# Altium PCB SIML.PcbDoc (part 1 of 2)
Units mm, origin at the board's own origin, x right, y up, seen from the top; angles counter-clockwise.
Board outline 80.5 x 51.25 mm, 2 copper layers (Top Layer, Top, Bottom Layer, Bottom), stack 1.571 mm thick; 94 components, 58 nets, 279 pads, 160 vias.
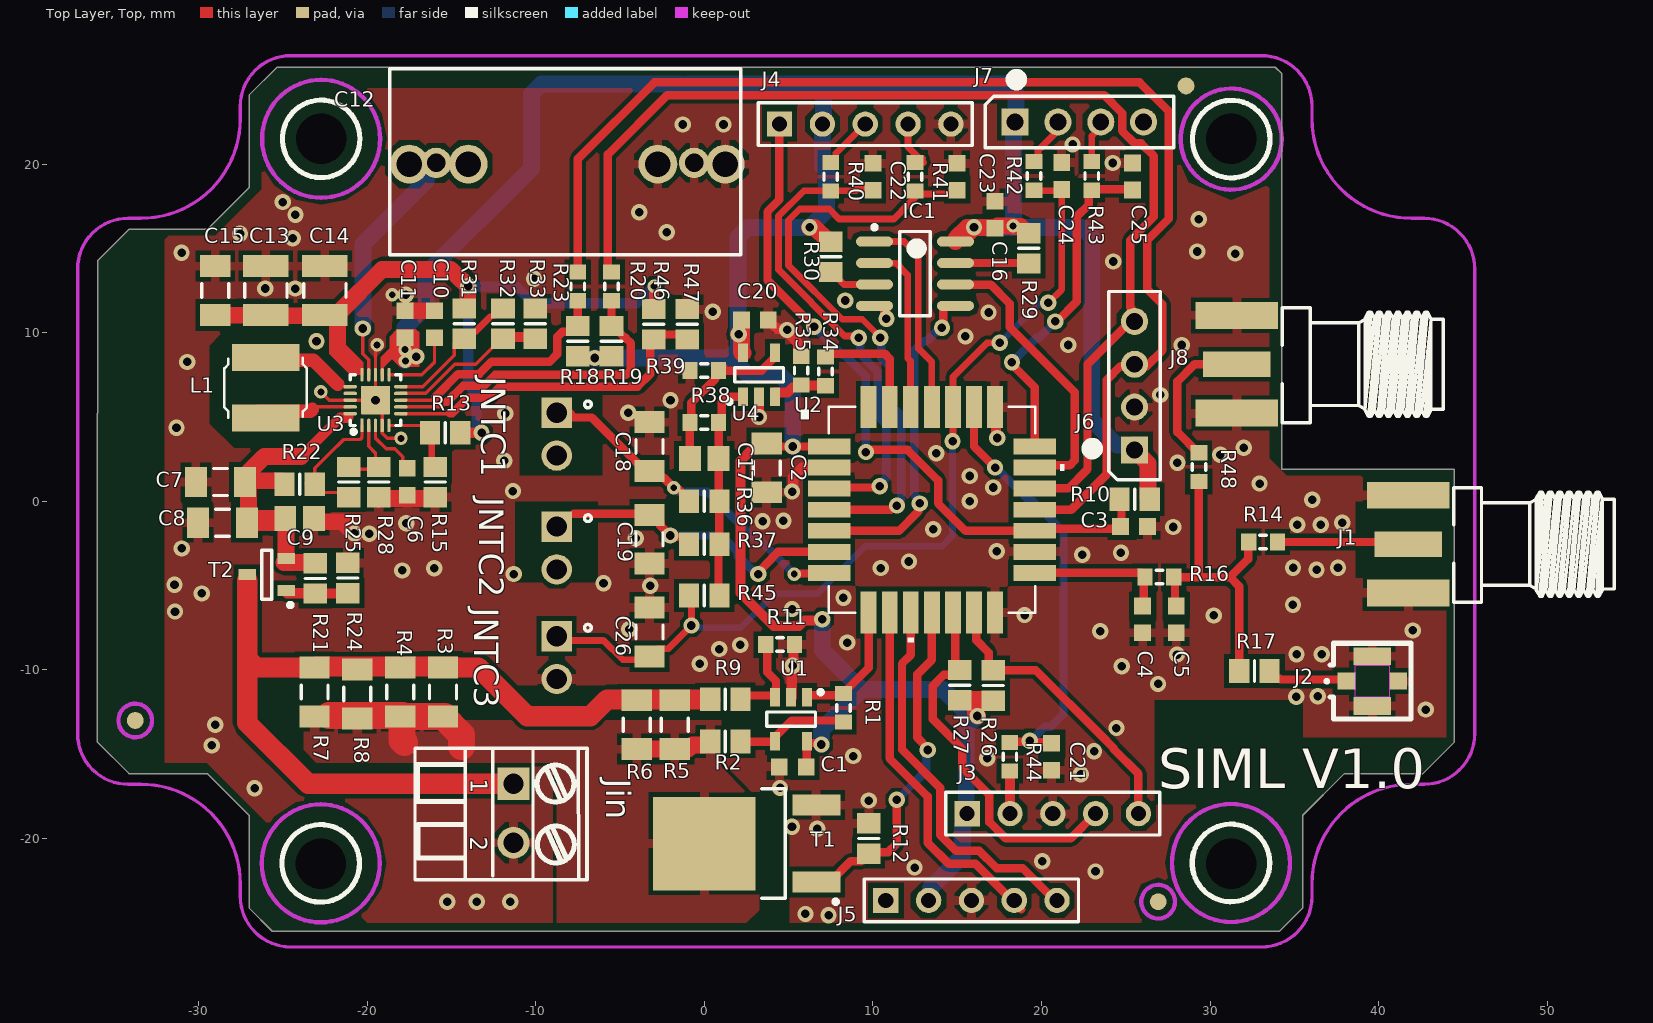
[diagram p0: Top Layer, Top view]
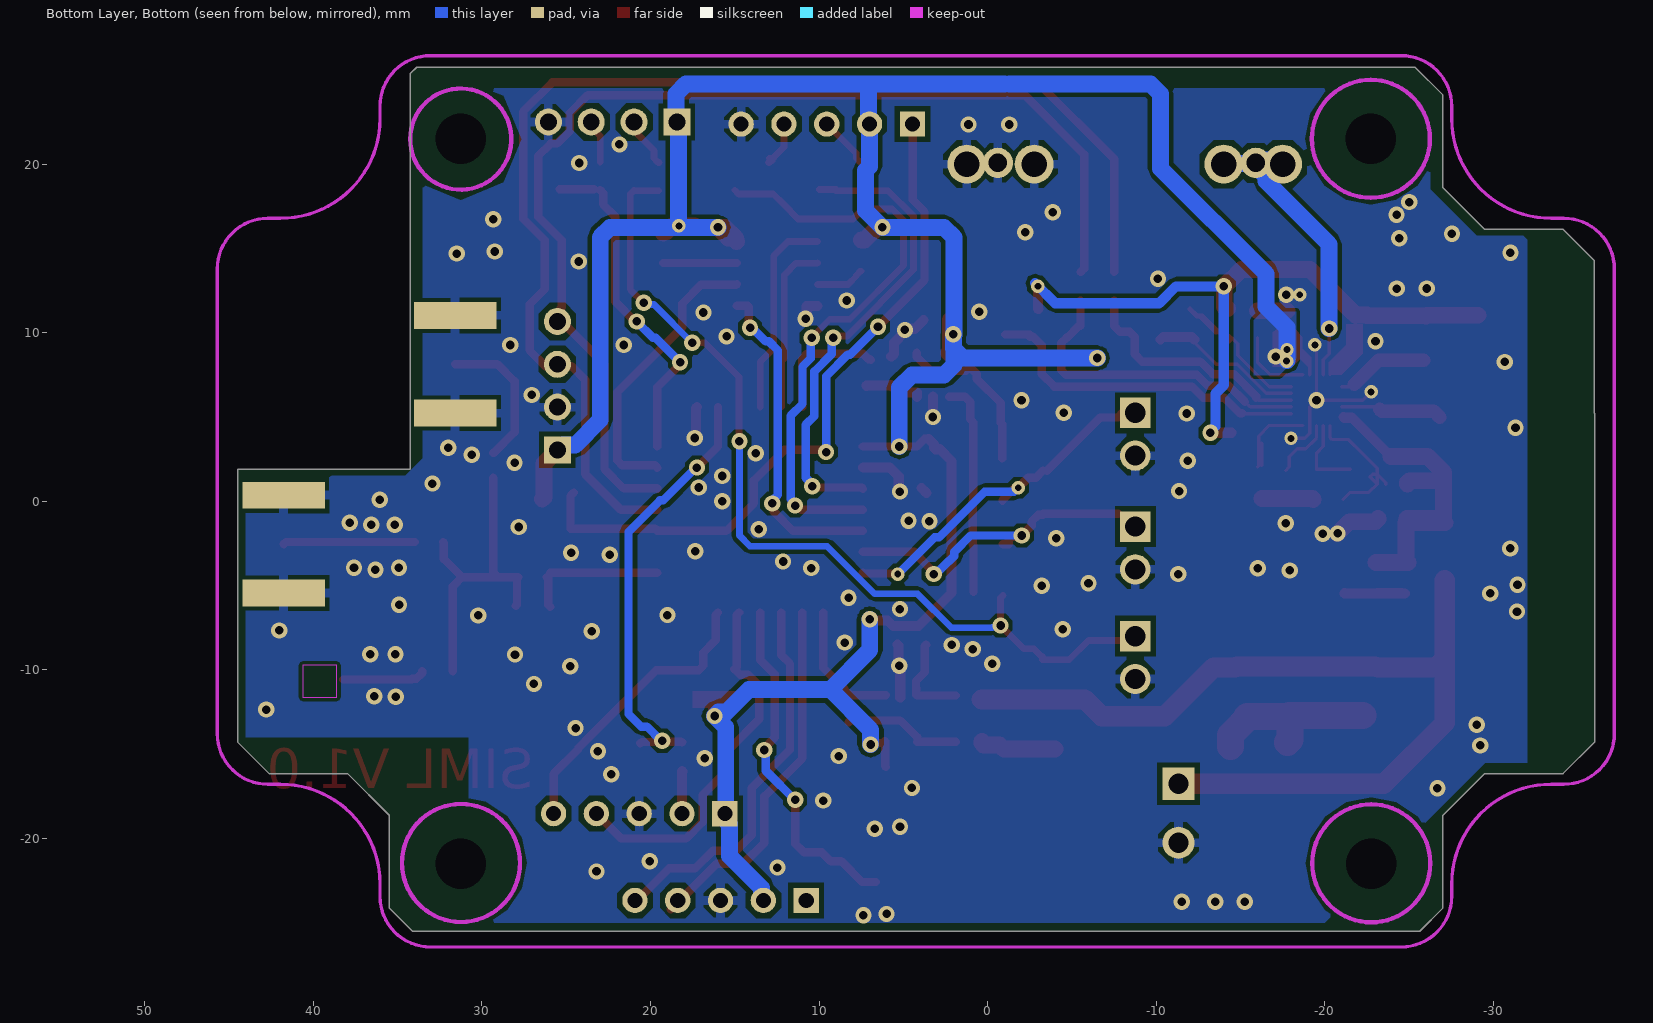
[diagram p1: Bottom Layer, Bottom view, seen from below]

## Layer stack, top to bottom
Top Solder, Top Mask: solder mask 0.0102, Solder Resist, Dk 3.5
Top Layer, Top: signal copper 0.0356
Dielectric 1: dielectric 1.5, FR-4, Dk 4.8
Bottom Layer, Bottom: signal copper 0.0356
Bottom Solder, Bot Mask: solder mask 0.0102, Solder Resist, Dk 3.5

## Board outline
-34.125,-16.15 -29.475,-16.15 -27,-18.625 -27,-24.125 -25.625,-25.5 34.125,-25.5 35.5,-24.125 35.5,-18.625 37.975,-16.15 42.625,-16.15 44.5,-14.275 44.5,1.905 34.25,1.905 34.25,25.375 33.875,25.75 -25.35,25.75 -26.975,24.125 -26.975,18.625 -29.45,16.15 -34.1,16.15 -35.975,14.275 -35.975,5.225 -36,5.225 -36,-14.275

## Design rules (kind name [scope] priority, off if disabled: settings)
Clearance Clearance_1 [All] p1: gap=0.22 ignorepadtopadclearanceinfootprint=FALSE except(0.2: Arc-SMDPad Track-Track Track-SMDPad SMDPad-SMDPad; 0.3: SMDPad-Poly THPad-Poly THPad-Region)
PlaneClearance [All] p1: clearance=0.254
PolygonConnect [All] p1: thpad.connectstyle=Relief thpad.reliefconductorwidth=0.54 thpad.reliefentries=4 thpad.polygonreliefangle="90 Angle" thpad.airgapwidth=0.254 smdpad.connectstyle=Relief smdpad.reliefconductorwidth=0.54 smdpad.reliefentries=4 smdpad.polygonreliefangle="90 Angle" smdpad.airgapwidth=0.254 via.connectstyle=Direct via.reliefconductorwidth=0.254 via.reliefentries=4 via.polygonreliefangle="90 Angle" via.airgapwidth=0.254
RoutingVias [All] p1: holewidth=1 width=1 viastyle="Through Hole" minholewidth=0.35 minwidth=0.8 maxholewidth=0.711 maxwidth=1.27
SilkToSilkClearance [All] p1: silktosilkclearance=0.1
SilkToSolderMaskClearance [IsPad] p1: minsilkscreentomaskgap=0.08 clearancetoexposedcopper=TRUE
SolderMaskExpansion [All] p1: expansion=0.102 istentingtop=FALSE
SupplyNets "Schematic Supply Nets_1" [InNet('3.3V')] p1: voltage=0.000
SupplyNets "Schematic Supply Nets" [InNet('GND')] p2: voltage=0.000
Width [All] p1: maxlimit=7.62 minlimit=0.2 preferedwidth=0.381
27 further rules are at their usual default settings.

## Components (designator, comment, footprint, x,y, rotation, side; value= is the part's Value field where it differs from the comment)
C1 "100nF" CAPC1608N 5.25,-15.75 r0 top
C2 "4.7uF" CAPC3216N 3.7,1.986 r90 top
C3 "100nF" CAPC1608N 25.5,-1.5 r180 top
C4 "N.M" CAPC1608N 26,-7 r90 top
C5 "N.M" CAPC1608N 28,-7 r90 top
C6 "10nF" CAPC1608N -17.613,1.163 r270 top
C7 "4.7uF" CAPC3216N -28.702,1.143 r0 top
C8 "4.7uF" CAPC3216N -28.575,-1.27 r0 top
C9 "N.M." CAPC2012N -24.003,-1.016 r180 top
C10 "100nF" CAPC1608N -16,10.5 r270 top
C11 "100nF" CAPC1608N -17.75,10.5 r270 top
C12 "5F" CAPR1530x1050X2050X2800 -8.25,20.075 r0 top locked
C13 "22uF" CAPC3225N -26,12.5 r270 top
C14 "22uF" CAPC3225N -22.5,12.5 r270 top
C15 "4.7uF" CAPC3216N -29,12.5 r270 top
C16 "100nF" CAPC1608N 17.25,17 r270 top
C17 "N.M." CAPC2012N 0,2.54 r0 top
C18 "4.7uF" CAPC3216N -3.25,3.25 r270 top
C19 "4.7uF" CAPC3216N -3.25,-2.25 r90 top
C20 "100nF" CAPC1608N 3,10.75 r180 top
C21 "N.M" CAPC1608N 20.6,-15.15 r270 top
C22 "N.M" CAPC1608N 10,19.25 r90 top
C23 "N.M" CAPC1608N 15,19.25 r90 top
C24 "N.M" CAPC1608N 21.209,19.304 r90 top
C25 "N.M" CAPC1608N 25.398,19.27 r90 top
C26 "4.7uF" CAPC3216N -3.25,-7.75 r270 top
IC1 "W25Q64JVSSIQ" SOIC127P600-8N 12.5,13.5 r0 top
J1 "SMA JACJK_EDGE_female" "Adam Tech_RF2-143-T-17-50-G" 43.18,-2.54 r180 top
J2 "U.FL-JACK_male" LINX_CONMHF1-SMD-T 39.624,-10.668 r90 top
J3 "HEADER 1X5" HDR1X5 20.675,-18.525 r0 top
J4 "HEADER 1X5" HDR1X5 9.55,22.375 r0 top
J5 "HEADER 1X5" HDR1X5 15.85,-23.675 r0 top
J6 "Header Female" HARWIN_M20-7820442 25.527,6.858 r90 top locked
J7 "Header Female" HARWIN_M20-7820442 22.25,22.5 r0 top
J8 "SMA JACJK_EDGE_female" "Adam Tech_RF2-143-T-17-50-G" 33.02,8.128 r180 top
Jin "DG381S" DEGSON_DG381S-3.5-02P-14-00AH -9,-18.5 r270 top
JNTC1 "CI31 Series 2.54mm(.100\")" CVILUX_CI3102P1V00 -8.75,5.25 r270 top
JNTC2 "CI31 Series 2.54mm(.100\")" CVILUX_CI3102P1V00 -8.75,-1.5 r270 top
JNTC3 "CI31 Series 2.54mm(.100\")" CVILUX_CI3102P1V00 -8.75,-8 r270 top
L1 "22uH" IND_Taiyo_NRS5024 -26.018,6.733 r90 top
R1 "49K9" RESC1608N(0603) 8.25,-12.25 r90 top
R2 "4K99" RESC2012N(0805) 1.25,-14.25 r0 top
R3 "1R" RESC3216N(1206) -15.494,-11.303 r270 top
R4 "1R" RESC3216N(1206) -18.034,-11.303 r270 top
R5 "1R" RESC3216N(1206) -1.75,-13.25 r270 top
R6 "1R" RESC3216N(1206) -4,-13.25 r270 top
R7 "1R" RESC3216N(1206) -23.114,-11.303 r270 top
R8 "1R" RESC3216N(1206) -20.574,-11.43 r270 top
R9 "4K99" RESC2012N(0805) 1.25,-11.75 r0 top
R10 "4K99" RESC2012N(0805) 25.527,0.127 r0 top
R11 "49K9" RESC1608N(0603) 4.5,-8.5 r180 top
R12 "4K99" RESC2012N(0805) 9.75,-20 r270 top
R13 "N.M." RESC2012N(0805) -15.367,4.064 r0 top
R14 "0R" RESC1608N(0603) 33.147,-2.413 r0 top
R15 "4K99" RESC2012N(0805) -15.953,1.143 r90 top
R16 "0R" RESC1608N(0603) 27,-4.5 r0 top
R17 "N.M." RESC2012N(0805) 32.635,-10.068 r0 top
R18 "4K99" RESC2012N(0805) -7.5,9.5 r270 top
R19 "4K99" RESC2012N(0805) -5.5,9.5 r270 top
R20 "0R" RESC1608N(0603) -5.5,12.75 r90 top
R21 "N.M." RESC2012N(0805) -23.075,-4.575 r90 top
R22 "10M" RESC2012N(0805) -24.003,1.016 r180 top
R23 "0R" RESC1608N(0603) -7.5,12.75 r90 top
R24 "4K99" RESC2012N(0805) -21.15,-4.55 r270 top
R25 "1M" RESC2012N(0805) -21.082,1.143 r270 top
R26 "2K2" RESC2012N(0805) 17.15,-10.925 r270 top
R27 "2K2" RESC2012N(0805) 15.159,-10.901 r270 top
R28 "5M6" RESC2012N(0805) -19.304,1.143 r90 top
R29 "4K99" RESC2012N(0805) 19.25,15 r90 top
R30 "4K99" RESC2012N(0805) 7.5,14.5 r90 top
R31 "6M2" RESC2012N(0805) -14.224,10.541 r90 top
R32 "499K" RESC2012N(0805) -11.938,10.541 r90 top
R33 "2M7" RESC2012N(0805) -10.033,10.541 r270 top
R34 "49K9" RESC1608N(0603) 7.2,7.7 r90 top
R35 "49K9" RESC1608N(0603) 5.75,7.75 r270 top
R36 "2K2" RESC2012N(0805) 0,0 r0 top
R37 "2K2" RESC2012N(0805) 0,-2.54 r0 top
R38 "49K9" RESC1608N(0603) 0,4.674 r0 top
R39 "49K9" RESC1608N(0603) 0,7.75 r0 top
R40 "0R" RESC1608N(0603) 7.5,19.25 r90 top
R41 "0R" RESC1608N(0603) 12.5,19.25 r90 top
R42 "0R" RESC1608N(0603) 19.558,19.304 r90 top
R43 "0R" RESC1608N(0603) 22.987,19.304 r90 top
R44 "0R" RESC1608N(0603) 18.125,-15.15 r270 top
R45 "2K2" RESC2012N(0805) 0,-5.588 r0 top
R46 "4K99" RESC2012N(0805) -3,10.5 r90 top
R47 "N.M." RESC2012N(0805) -1,10.5 r270 top
R48 "0R" RESC1608N(0603) 29.337,2.032 r90 top
T1 "IRLR8726PBF" TO228P991X239-3N-R546X521 2.5,-20.3 r180 top
T2 "AP2311GN-HF-3TR" SOT95P240X130-3N -25.95,-4.35 r180 top
U1 "TLV333IDBVR" SOT95P280X145-5N 5.151,-12.921 r270 top
U2 "114993121" QFN_90687_SEE-L 13.5,-0.5 r0 top
U3 "SPV1050TTR" QFN40P300X300X100-21N -19.5,6 r90 top
U4 "MCP6071T-E/OT" SOT95P280X145-5N 3.25,7.5 r90 top

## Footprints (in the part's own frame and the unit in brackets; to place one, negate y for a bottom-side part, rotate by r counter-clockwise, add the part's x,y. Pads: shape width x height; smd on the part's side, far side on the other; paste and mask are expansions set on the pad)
"Adam Tech_RF2-143-T-17-50-G" [mm] "SMA End Launch Jack for 1.58mm PCB, 50 Ohm, Flat Tab Contact"
  rect 4x1.5 smd: 1(1.425,0)
  rect 4.9x1.6 smd: 2(1.425,2.9) 2(1.425,-2.9)
  rect 4.9x1.6 smd far side: 2(1.425,2.9) 2(1.425,-2.9)
  silkscreen extent -10.81,-3.34 -1.28,3.46, body extent -11.06,-3.18 2.25,3.18, height 3.57
CAPC1608N [mm] "Chip Capacitor, Body 1.6x0.8mm, IPC Medium Density"
  rect 1x1 smd: 1(-0.8,0) 2(0.8,0)
  body extent -0.87,-0.48 0.87,0.48, height 0.85
CAPC2012N [mm] "Chip Capacitor, Body 2.0x1.3mm, IPC Medium Density"
  rect 1.3x1.5 smd: 1(-0.85,0) 2(0.85,0)
  body extent -1.1,-0.72 1.1,0.72, height 1.1
CAPC3216N [mm] "Chip Capacitor, Body 3.2x1.6mm, IPC Medium Density"
  rect 1.3x1.8 smd: 1(-1.45,0) 2(1.45,0)
  silkscreen extent -0.4,-0.8 0.4,0.8, body extent -1.7,-0.9 1.7,0.9, height 1.35
CAPC3225N [mm] "Chip Capacitor, Body 3.2x2.5mm, IPC Medium Density"
  rect 1.3x2.7 smd: 1(-1.45,0) 2(1.45,0)
  silkscreen extent -0.4,-1.25 0.4,1.25, body extent -1.7,-1.35 1.7,1.35, height 1.35
CAPR1530x1050X2050X2800 [mm] "Capacitor Radial, Pin spacing 15.0mm - Body Width 9mm X Body Length 18mm X Body Height 17.5mm"
  round 1.8 hole 1.1: 1(-7.65,0) 2(7.65,0)
  silkscreen extent -10.41,-5.46 10.41,5.59, body extent -10.25,-5.17 10.25,5.33, height 27.5
CVILUX_CI3102P1V00 [mm]
  rect 1.8x1.8 hole 1.2: 1(0,0)
  round 1.8 hole 1.2: 2(2.54,0)
  silkscreen extent -0.7,1.65 -0.3,2.05, body extent -1.23,-3.2 3.87,2.6, height 11.53
DEGSON_DG381S-3.5-02P-14-00AH [mm]
  rect 1.9x1.9 hole 1.2: 1(-1.747,-2.311)
  round 1.9 hole 1.2: 2(1.753,-2.311)
  silkscreen extent -3.86,-8.15 3.94,2.06, body extent -3.71,-7.97 3.79,2.03, height 9.63
HARWIN_M20-7820442 [mm] "4-Contacts - Pitch 2.54mm - Single Row  Through Mount Header  Socket Total Height 8.64mm"
  rect 1.6x1.6 hole 1: 1(-3.81,0)
  round 1.6 hole 1: 2(-1.27,0) 3(1.27,0) 4(3.81,0)
  silkscreen extent -5.59,-1.52 5.59,2.65, body extent -5.28,-1.25 5.28,1.25, height 8.5
HDR1X5 [mm]
  rect 1.5x1.5 hole 0.9: 1(-5.08,0)
  round 1.5 hole 0.9: 2(-2.54,0) 3(0,0) 4(2.54,0) 5(5.08,0)
  silkscreen extent -6.35,-1.27 6.35,1.27
IND_Taiyo_NRS5024 [mm] "Inductor  NRS5024   Series ±20%, 0.82A, 4.9x4.9x2.4mm"
  rect 1.6x4 smd paste-0.152: 1(-1.8,0) 2(1.8,0)
  silkscreen extent -1.77,-2.45 1.77,2.45, body extent -2.45,-2.45 2.45,2.45, height 2.4
LINX_CONMHF1-SMD-T [mm]
  rect 1x1.05 smd: 1(0,1.525) 4(0,-1.525)
  rect 1.05x2.2 smd: 2(1.475,0) 3(-1.475,0)
  Keep-Out Layer, Board region: 0.95,-1 -0.95,-1 -0.95,1 0.95,1
  Keep-Out Layer, Board region: 0.95,-1 -0.95,-1 -0.95,1 0.95,1
  silkscreen extent -2.25,-2.3 2.25,2.8, body extent -1.5,-1.55 1.5,1.55, height 1.31
QFN40P300X300X100-21N [mm]
  rect 0.8x0.2 smd mask+0.07: 1(-1.5,0.8)
  oval 0.8x0.2 smd mask+0.07: 2(-1.5,0.4) 3(-1.5,0) 4(-1.5,-0.4) 5(-1.5,-0.8) 11(1.5,-0.8) 12(1.5,-0.4) 13(1.5,0) 14(1.5,0.4) 15(1.5,0.8)
  oval 0.2x0.8 smd mask+0.07: 6(-0.8,-1.5) 7(-0.4,-1.5) 8(0,-1.5) 9(0.4,-1.5) 10(0.8,-1.5) 16(0.8,1.5) 17(0.4,1.5) 18(0,1.5) 19(-0.4,1.5) 20(-0.8,1.5)
  rrect4% 1.7x1.7 smd paste-2 mask+0.07: 21(0,0)
  silkscreen extent -2,-1.5 1.5,1.5, body extent -1.5,-1.5 1.5,1.5, height 1
QFN_90687_SEE-L [mil]
  rect 99x37 smd paste+0 mask+0: 1(-240,147.64) 2(-240,98.43) 3(-240,49.21) 4(-240,0) 5(-240,-49.21) 6(-240,-98.43) 7(-240,-147.64) 15(240,-147.64) 16(240,-98.43) 17(240,-49.21) 18(240,0) 19(240,49.21) 20(240,98.43) 21(240,147.64)
  rect 37x99 smd paste+0 mask+0: 8(-147.64,-240) 9(-98.43,-240) 10(-49.21,-240) 11(0,-240) 12(49.21,-240) 13(98.43,-240) 14(147.64,-240) 22(147.64,240) 23(98.43,240) 24(49.21,240) 25(0,240) 26(-49.21,240) 27(-98.43,240) 28(-147.64,240)
  silkscreen extent -241,-310 310,241, body extent -281,-281 281,281, height 98
RESC1608N(0603) [mm] "Chip Resistor, Body 1.6x0.8mm, IPC Medium Density"
  rect 0.9x1 smd: 1(-0.85,0) 2(0.85,0)
  silkscreen extent -0.2,-0.4 0.2,0.4, body extent -0.85,-0.48 0.85,0.48, height 0.6
RESC2012N(0805) [mm] "Chip Resistor, Body 2.0x1.3mm, IPC Medium Density"
  rect 1.2x1.4 smd: 1(-0.9,0) 2(0.9,0)
  silkscreen extent 0,-0.6 0,0.6, body extent -1.07,-0.7 1.07,0.7, height 0.65
RESC3216N(1206) [mm] "Chip Resistor, Body 3.2x1.6mm, IPC Medium Density"
  rect 1.3x1.8 smd: 1(-1.45,0) 2(1.45,0)
  silkscreen extent -0.4,-0.8 0.4,0.8, body extent -1.68,-0.87 1.68,0.87, height 0.71
SOIC127P600-8N [mm] "SOIC, 8-Leads, Body 4.9x3.9mm, Pitch 1.27mm, IPC Medium Density"
  oval 2.2x0.6 smd: 1(-2.4,1.905) 2(-2.4,0.635) 3(-2.4,-0.635) 4(-2.4,-1.905) 5(2.4,-1.905) 6(2.4,-0.635) 7(2.4,0.635) 8(2.4,1.905)
  silkscreen extent -2.52,-2.5 0.9,2.88, body extent -3.1,-2.5 3.1,2.5, height 1.75
SOT95P240X130-3N [mm] "SOT23 3-Leads, Pitch 0.95mm - Body 1.3x2.9mm, IPC Medium Density"
  rect 1.05x0.65 smd: 1(-1.15,0.95) 2(-1.15,-0.95) 3(1.15,0)
  silkscreen extent -1.53,-1.45 0.3,1.92, body extent -1.25,-1.5 1.25,1.5, height 1.3
SOT95P280X145-5N [mm] "SOT, 0.95mm pitch; 5 pin, 1.60mm W X 2.90mm L X 1.45mm H body, IPC Medium Density"
  rect 1.1x0.6 smd: 1(-1.3,0.95) 2(-1.3,0) 3(-1.3,-0.95) 4(1.3,-0.95) 5(1.3,0.95)
  silkscreen extent -1.72,-1.45 0.43,1.88, body extent -1.4,-1.5 1.4,1.5, height 1.45
TO228P991X239-3N-R546X521 [mm] "TO-252AA DPAK TO, 2.28mm pitch; 2 pin,9.905mm L X 6.095mm W X 2.39mm H body, IPC Medium Density"
  rect 2.85x1.25 smd: 1(-4.15,2.28) 2(-4.15,-2.28)
  rect 6.1x5.55 smd: 3(2.5,0)
  silkscreen extent -5.43,-3.25 -0.9,3.57, body extent -4.99,-3.27 4.95,3.27, height 2.28

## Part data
C1 C3 C10 C11 C16 C20: library part CC0603_100NF_50V_10%_X7R, "Non-polarised capacitor", Case=0603, Comment_Ratings="100nF / 50V", Manufacturer=GENERIC, Manufacturer1 ComponentHeight=0.87mm, Manufacturer1 Example=TDK, Manufacturer1 Part Number=C1608X7R1H104K080AA, Tolerance=±10%, Voltage=50V
C2 C7 C8 C15 C18 C19 C26: library part CC1206_4.7UF_50V_10%_X7R, "Non-polarised capacitor", Case=1206, Comment_Ratings="4.7uF / 50V", Manufacturer=GENERIC, Manufacturer1 ComponentHeight=1.60mm, Manufacturer1 Example=TDK, Manufacturer1 Part Number=C3216X7R1H475K160AC, Tolerance=±10%, Voltage=50V
C4 C5 C21 C22 C23 C24 C25: library part CC0603_NO-VALUE, "Non-polarised capacitor", Case=0603, Manufacturer=GENERIC, Manufacturer1 ComponentHeight=0.87mm
C6: library part CC0603_10NF_50V_10%_X7R, "Non-polarised capacitor", Case=0603, Comment_Ratings="10nF / 50V", Manufacturer=GENERIC, Manufacturer1 ComponentHeight=0.87mm, Manufacturer1 Example=TDK, Manufacturer1 Part Number=C1608X7R1H103K080AA, Tolerance=±10%, Voltage=50V
C9 C17: library part CC0805_NO-VALUE, "Non-polarised capacitor", Case=0805, Manufacturer=Undefined, Manufacturer1 ComponentHeight=1.35mm
C12: library part CAER_5F_5.5V_0%+30%, "Polarised capacitor", Case="LS15.3 D20.5 x T10.5 x H28", Comment_Ratings="5F / 5.5V", Manufacturer="Abracon LLC", Manufacturer Part Number=ADCM-S05R5SA505RB, Tolerance=0%+30%, Voltage=5.5V
C13 C14: library part CC1210_22UF_16V_10%_X7R, "Non-polarised capacitor", Case=1210, Comment_Ratings="22uF / 16V", Manufacturer=GENERIC, Manufacturer1 ComponentHeight=2.50mm, Manufacturer1 Example=TDK, Manufacturer1 Part Number=C3225X7R1C226K250AC, Manufacturer Part Number=CC1210_22UF_10V_10%_X7R, Tolerance=±10%, Voltage=16V
IC1: "FLASH - NOR Memory IC 64Mbit SPI - Quad I/O 133 MHz 8-SOIC", Case=SOIC8, Manufacturer="Winbond Electronics"
J1 J8: library part "Adam Tech_RF2-143-T-17-50-G_SMA", Manufacturer="Adam Tech", Manufacturer Part Number=RF2-143-T-17-50-G
J2: library part "TE Connectivity_CONMHF1-SMD-T_U.FL", Manufacturer="TE Connectivity Linx", Manufacturer Part Number=CONMHF1-SMD-T
J3 J4 J5: library part "HEADER 1 X 5_2.54MM", "Connector 5 Male", Manufacturer Part Number="DO NOT MOUNT"
J6 J7: library part M20-7820442, "Connector 4 Female", Manufacturer=HARWIN
Jin: library part DEGSON_DG381S-3.5-02P-14-00AH, "Terminal Block, 2 Positions, Screw Connection", Comment_Ratings="300V / 10A / 16-26 AWG", Manufacturer=DEGSON, Manufacturer Part Number=DG381S-3.5-02P-14-00AH
JNTC1 JNTC2 JNTC3: library part CVILUX_CI3102P1V00, "Connector 2 Male", Manufacturer=CVILUX, Manufacturer Part Number=CI3102P1V00
L1: library part IND_22UH_20%_Taiyo-Yuden_NRS5024T220MMGJV, "Inductor", Case=NRS5024, Comment_Ratings="22uH / 0.82A", Manufacturer="Taiyo Yuden", Manufacturer Part Number=NRS5024T220MMGJV, Power=820mA, Resistance=0.276R, Tolerance=±20%
R1 R11 R34 R35 R38 R39: library part R0603_49K9_1%_0.1W_100PPM, "Resistor-1%", Case=0603, Comment_Ratings="49K9 / 0.1W", Manufacturer=GENERIC, Manufacturer1 ComponentHeight=0.55mm, Manufacturer1 Example="YAGEO PHYCOMP", Manufacturer1 Part Number=RC0603FR-0749K9L, Power=0.1W, Tolerance=±1%
R2 R9 R10 R12 R15 R18 R19 R24 R29 R30 R46: library part R0805_4K99_1%_0.125W_100PPM, "Resistor-1%", Case=0805, Comment_Ratings="4K99 / 0.125W", Manufacturer="Vishay Dale", Manufacturer1 ComponentHeight=0.5mm, Manufacturer1 Example=VISHAY, Manufacturer1 Part Number=CRCW08054K99FKEA, Power=0.125W, Tolerance=±1%
R3 R4 R5 R6 R7 R8: library part R1206_1R_0.5%_0.52W_25PPM, "Resistor-0.1%", Case=1206, Comment_Ratings="1R / 0.52W / 25PPM", Manufacturer=YAGEO, Manufacturer1 ComponentHeight=TNPW12061R00DEEA, Manufacturer1 Example=VISHAY, Manufacturer1 Part Number="RES 1 OHM 0.5% 0.52W 1206", Power=0.25W, Tolerance=±0.5%
R13 R17 R21 R47: library part R0805_NO-VALUE, "Resistor", Case=0805, Manufacturer=Undefined
R14 R16 R20 R23 R40 R41 R42 R43 R44 R48: library part R0603_0R_JUMPER, "Resistor", Case=0603, Comment_Ratings="0R / 1A Max", Manufacturer=GENERIC, Manufacturer1 ComponentHeight=0.55mm, Manufacturer1 Example="YAGEO PHYCOMP", Manufacturer1 Part Number=RC0603JR-070RL
R22: library part R0805_10M_1%_0.125W_100PPM, "Resistor-1%", Case=0805, Comment_Ratings="10M / 0.125W", Manufacturer="Vishay Dale", Manufacturer1 ComponentHeight=0.5mm, Manufacturer1 Example=VISHAY, Manufacturer1 Part Number=CRCW080510M00FKEA, Power=0.125W, Tolerance=±1%
R25: library part R0805_1M_1%_0.125W_100PPM, "Resistor-1%", Case=0805, Comment_Ratings="1M / 0.125W", Manufacturer="Vishay Dale", Manufacturer1 ComponentHeight=0.5mm, Manufacturer1 Example=VISHAY, Manufacturer1 Part Number=CRCW08051M00FKEA, Power=0.125W, Tolerance=±1%
R26 R27 R36 R37 R45: library part R0805_2K2_1%_0.125W_100PPM, "Resistor-1%", Case=0805, Comment_Ratings="2K2 / 0.125W", Manufacturer=GENERIC, Manufacturer1 ComponentHeight=0.65mm, Manufacturer1 Example="YAGEO PHYCOMP", Manufacturer1 Part Number=RC0805FR-072K2L, Power=0.125W, Tolerance=±1%
R28: library part R0805_5M6_1%_0.125W_100PPM, "Resistor-1%", Case=0805, Comment_Ratings="5M6 / 0.125W", Manufacturer="Vishay Dale", Manufacturer1 ComponentHeight=0.5mm, Manufacturer1 Example=VISHAY, Manufacturer1 Part Number=CRCW08055M60FKEA, Power=0.125W, Tolerance=±1%
R31: library part R0805_6M2_1%_0.125W_100PPM, "Resistor-1%", Case=0805, Comment_Ratings="6M2 / 0.125W", Manufacturer="Vishay Dale", Manufacturer1 ComponentHeight=0.5mm, Manufacturer1 Example=VISHAY, Manufacturer1 Part Number=CRCW08056M20FKEA, Power=0.125W, Tolerance=±1%
R32: library part R0805_499K_1%_0.125W_100PPM, "Resistor-1%", Case=0805, Comment_Ratings="499K / 0.125W", Manufacturer=GENERIC, Manufacturer1 ComponentHeight=0.65mm, Manufacturer1 Example="YAGEO PHYCOMP", Manufacturer1 Part Number=RC0805FR-07499KL, Power=0.125W, Tolerance=±1%
R33: library part R0805_2M7_1%_0.125W_100PPM, "Resistor-1%", Case=0805, Comment_Ratings="2M7 / 0.125W", Manufacturer="Vishay Dale", Manufacturer1 ComponentHeight=0.5mm, Manufacturer1 Example=VISHAY, Manufacturer1 Part Number=CRCW08052M70FKEA, Power=0.125W, Tolerance=±1%
T1: "N-channel FET transistor in SOT-23", Case=TO252-AA, Comment_Ratings="Vds{}30V / Id{}86A", Manufacturer="INFINEON TECHNOLOGIES"
T2: "P-channel FET transistor in SOT-23", Case=SOT23-2, Comment_Ratings="Vds{}60V / Id{}1.8A", Manufacturer="ADVANCED POWER ELECTR. CO"
U1: "Single Op Amp in SOT23/5", Case=SOT23-5, Manufacturer="TEXAS INSTRUMENTS"
U2: library part 114993121_RF_SEED, "WIO-E5-LE WIRELESS MODULE (TAPE)", Manufacturer="Seeed Technology Co., Ltd", Mfr_Name=BeagleBoard
U3: "Charger IC Multi-Chemistry 20-VFQFPN (3x3)", Case=20-VFQFN, Manufacturer=STMicroelectronics, Package="VFQFN-20 STMicroelectronics"
U4: "Single Op Amp in SOT23/5", Case=SOT23-5, Manufacturer="Analog Devices"

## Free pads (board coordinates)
  round 2.3 hole 1.5 paste-2539.97: 1(-17.5,20) 1(-14,20) 1(-2.75,20) 1(1.25,20)
  oval 0.8x0.5 hole 3: 20(-22.75,-21.5) 20(-22.725,21.5) 20(31.25,-21.5) 20(31.25,21.5)
  round 1 smd paste-0.51 mask+0.5: Fid(-33.75,-13) Fid(26.924,-23.749) Fid(28.575,24.638)

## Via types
v1: diameter 0.965, hole 0.508, Top Layer, Top to Bottom Layer, Bottom, tented both sides, 146 vias
v2: diameter 0.8, hole 0.4, Top Layer, Top to Bottom Layer, Bottom, tented both sides, 10 vias
v3: diameter 0.965, hole 0.508, Top Layer, Top to Bottom Layer, Bottom, 4 vias

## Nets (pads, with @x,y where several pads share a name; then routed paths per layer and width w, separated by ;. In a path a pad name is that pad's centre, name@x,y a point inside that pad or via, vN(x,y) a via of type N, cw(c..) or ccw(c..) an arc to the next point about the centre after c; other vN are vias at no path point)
3.3V: C1.2 C2.2 C11.2 C16.2 C20.2 IC1.8 J3.1 J4.2 J5.2 J6.1 J7.1 R10.2 R18.2 R19.2 R26.2 R27.2 R29.2 R30.2 U1.5 U2.1 U3.12 U4.5 | length 182.1
  Top Layer, Top w0.2: U3.12@-19.1,7.5 -19.1,8.15 -18.15,9.1 -18.15,9.357 C11.2@-17.75,9.757
  Top Layer, Top w0.5: C2.2@3.75,3.7 4.2,3.25 v1(5.25,3.25) U2.1@7.404,3.25 ; C1.2@6.05,-15.75 6.075,-15.725 6.075,-14.246 U1.5@6.101,-14.221 6.101,-14.284 6.151,-14.334 6.862,-14.334 v1(6.951,-14.423)
  Top Layer, Top w0.6: C2.2@3.5,3.7 3.186,3.386 3.186,3.172 3.1,3.086 2.836,3.086 2.145,2.395 2.145,-5.433 4.105,-7.393 5.626,-7.393 5.949,-7.07 6.93,-7.07 v1(7,-7)
  Top Layer, Top w1: v1(2.041,9.908) v1@2.2,10.067 ; C20.2@2.2,10.75 v1@2.2,10.067 ; U4.5@2.3,8.8 2.25,8.8 2.2,8.85 v1@2.2,10.067 ; v1(6.25,16.25) 6.55,16.25 7.3,15.5 R30.2@7.5,15.5 ; IC1.8@14.9,15.405 15.1,15.605 15.414,15.605 15.414,15.665 v1(16,16.25) 17.3,16.25 17.382,16.332 v2(18.32,16.332) ; IC1.8@14.968,15.635 15.583,16.25 v1(16,16.25) ; 16.088,-11.787 16.088,-12.621 v1(16.202,-12.735) ; v2@18.32,16.3 18.75,16.3 19.05,16 19.15,16 R29.2@19.25,15.9 ; J6.1@25.527,3.048 26.327,2.248 26.327,0.227 R10.2@26.427,0.127
  Bottom Layer, Bottom w1: v2@-17.75,8.342 v2(-17.75,9) -17.75,10.299 -16.5,11.549 -16.5,13.5 -10.25,19.75 -10.25,24.164 -9.664,24.75 -1.287,24.75 ; v1(-6.5,8.5) 1.473,8.5 2,9.027 ; -1,24.75 7.079,24.75 ; 2,9.068 2,9.027 ; v1@2,9.867 2,15.664 2.586,16.25 v1(6.25,16.25) 7.25,17.25 7.25,19.625 7.01,19.865 J4.2@7.01,22.375 ; v1(2.041,9.908) 2.041,9.068 2,9.027 ; v1(5.25,3.25) 5.25,6.75 4.5,7.5 2.586,7.5 2,8.086 2,9.027 ; v1(6.951,-14.423) 6.951,-13.549 9.336,-11.164 ; v1(7,-7) 7,-8.828 9.336,-11.164 ; J4.2@7.079,22.444 7.079,24.75 ; J5.2@13.335,-23.825 13.431,-23.729 13.431,-22.944 15.325,-21.05 15.325,-19.145 J3.1@15.545,-18.925 ; J3.1@15.545,-18.775 15.545,-13.393 v1(16.202,-12.735) 15.967,-12.5 15.75,-12.5 ; 15.625,-12.625 14.164,-11.164 9.336,-11.164 ; v1(16,16.25) 22.401,16.25 22.987,15.664 22.987,4.826 24.465,3.348 25.227,3.348 J6.1@25.527,3.048 ; v2(18.32,16.332) 18.34,16.352 J7.1@18.34,22.275 ; J7.1@18.5,22.505 18.5,24.164 17.914,24.75 7.079,24.75
  other v1: -17.079,8.583
  other v2: -17.727,8.319
AD1CH0: C24.1 C26.2 JNTC3.1 R42.1 R45.1 U2.24 | length 53.5
  Top Layer, Top w0.4: JNTC3.1@-8,-8.25 -5.974,-8.25 -4.826,-9.398 C26.2@-3.25,-9.398 ; C26.2@-3.25,-9.2 -3.198,-9.2 -2.748,-8.75 -2.146,-8.75 v1(-0.762,-7.366) -0.762,-5.726 R45.1@-0.9,-5.588 ; v1(14.732,3.556) 14.75,3.574 14.75,7.384 16.764,9.398 v3(17.526,9.398) ; R42.1@19.525,18.425 C24.1@21,18.425 ; v3(20.412,11.778) 21.209,12.575 21.209,18.204 21,18.413 C24.1@21,18.45
  Bottom Layer, Bottom w0.4: v1@-0.666,-7.5 -0.641,-7.474 -0.271,-7.474 -0.245,-7.5 2.152,-7.5 4.164,-5.488 6.704,-5.488 9.525,-2.667 14.097,-2.667 14.732,-2.032 v1(14.732,3.556) ; v3(17.526,9.398) 19.798,11.67 20.304,11.67 v3(20.412,11.778)
AD1CH2: R1.2 U1.1 U2.8 | length 7.6
  Top Layer, Top w0.5: U1.1@6.051,-11.5 R1.2@8.25,-11.5 ; R1.2@8.25,-11.379 8.321,-11.379 8.5,-11.2 8.5,-11.129 9.75,-9.879 U2.8@9.75,-6.596
AD1CH3: C18.2 JNTC1.1 R36.1 U2.7 | length 20.1
  Top Layer, Top w0.5: JNTC1.1@-8.009,5.25 -7.728,4.97 -6.67,4.97 C18.2@-3.5,1.8 ; C18.2@-3.25,1.8 -2.85,1.4 -2.4,1.4 -1.75,0.75 -1.55,0.75 -0.875,0.075 R36.1@-0.875,0.025 ; v2(5.334,-4.318) 5.368,-4.284 7.37,-4.284 U2.7@7.404,-4.25
  Bottom Layer, Bottom w0.5: v2@-1.557,0.557 0.193,0.557 2.893,-2.143 3.159,-2.143 v2(5.334,-4.318)
  other v2: -1.807,0.807
AD1CH11: C19.2 JNTC2.1 R37.1 U2.6 | length 19.1
  Top Layer, Top w0.5: -7.75,-0.75 -3.3,-0.75 C19.2@-3.25,-0.8 -3,-0.8 -2.6,-1.2 -2.6,-1.45 v1(-2.022,-2.028) -1.933,-2.117 -1.25,-2.117 -1.234,-2.134 -1.234,-2.54 R37.1@-0.9,-2.54 ; v1(3.209,-4.318) 3.209,-4.192 4.005,-3.396 4.005,-3.361 4.366,-3 U2.6@7.404,-3
  Bottom Layer, Bottom w0.5: v1(-2.022,-2.028) 1.012,-2.028 1.986,-3.002 1.986,-3.255 2.253,-3.522 2.287,-3.522 3.083,-4.318 v1(3.209,-4.318)
BAT_CHG: J6.4 R20.2 U2.19 | length 66.9
  Top Layer, Top w0.5: R20.2@-5.5,13.6 -5.515,13.6 -5.715,13.8 -5.715,20.574 -2.207,24.082 23.734,24.082 24.79,23.026 24.79,21.974 25.534,21.23 25.912,21.23 26.67,20.472 26.67,16.891 25.273,15.494 25.273,11.511 25.317,11.467 25.317,10.712 22.733,8.128 22.733,1.899 21.603,0.769 19.615,0.769 U2.19@19.596,0.75
BAT_CON: J6.3 R23.2 U2.18 | length 74.1
  Top Layer, Top w0.5: R23.2@-7.5,13.6 -7.5,20.313 -2.961,24.852 25.821,24.852 27.559,23.114 27.559,16.764 26.289,15.494 26.289,12.573 27.178,11.684 27.178,8.948 J6.3@26.25,8.02 ; U2.18@19.596,-0.5 21.77,-0.5 23.876,1.606 23.876,7.196 24.7,8.02 25.527,8.02 J6.3@26.17,8.02
DACOUT1: R34.2 U2.27 | length 7.2
  Top Layer, Top w0.5: R34.2@6.95,8.4 6.975,8.425 7.075,8.425 7.4,8.75 10.707,8.75 11,8.457 U2.27@11,5.596
GND: C1.1 C2.1 C3.1 C4.1 C5.1 C6.2 C7.1 C8.1 C9.1 C10.1 C11.1 C12.2 C13.1 C14.1 C15.1 C16.1 C18.1 C19.1 C20.1 C21.2 C22.2 C23.2 C24.2 C25.2 C26.1 IC1.4 J1.2 J2.2 J2.3 J2.4 J3.3 J4.5 J5.3 J6.2 J7.4 J8.2 Jin.2 JNTC1.2 JNTC2.2 JNTC3.2 pad.1@1.25,20 pad.1@-2.75,20 R11.1 R12.1 R15.1 R24.1 R28.1 R33.1 R35.1 R39.1 R47.1 T1.2 U1.2 U2.2 U2.14 U2.16 U2.22 U3.4 U3.13 U3.18 U3.21 U4.2 | length 32.6
  Top Layer, Top w0.2: v2(-22.738,6.488) -22.723,6.488 -22.236,6 U3.18@-21,6 v1(-19.5,6) ; v2(-19.409,9.275) -19.5,9.184 v1(-19.5,6) ; v2(-17.987,3.732) -18.005,3.75 -18.816,3.75 -19.1,4.034 U3.4@-19.1,4.5 -19.1,5.6 v1(-19.5,6)
  Top Layer, Top w0.6: v1(3.25,5) U4.2@3.25,6.2 ; C2.1@3.644,0.5 C2.1@3.933,0.789 ; C20.1@3.8,10.75 4.315,10.235 4.844,10.235 4.984,10.095 4.984,9.98 5.55,9.414 5.55,8.75 5.7,8.6 R35.1@5.75,8.6 ; U1.2@5.193,-11.621 5.193,-9.807 v1(5.25,-9.75) 5.3,-9.7 5.3,-8.55 R11.1@5.35,-8.5 ; v1(5.21,0.578) 5.28,0.648 5.28,1.475 5.805,2 U2.2@7.404,2 ; IC1.4@10.1,11.595 10.737,11.595 10.737,10.9 v1(10.807,10.83) ; U2.22@17.25,5.596 17.314,5.532 17.314,3.819 v1(17.378,3.755)
  Top Layer, Top w0.8: JNTC3.2@-8.907,-10.697 JNTC3.2@-8.75,-10.54
  Top Layer, Top w1: C9.1@-23.153,-1.016 -23.153,-1.06 -23.003,-1.21 -21.446,-1.21 v1(-20.751,-1.905) ; R28.1@-19.304,0.116 -19.254,0.166 R15.1@-16.256,0.166 ; C11.1@-17.75,11.3 C10.1@-16,11.3
  other v1: 7.375,-24.55 6,-24.475 -15.25,-23.75 -13.5,-23.75 -11.5,-23.75 23.205,-21.955 12.475,-21.725 20.054,-21.356 6.7,-19.425 5.207,-19.304 9.75,-17.75 -26.67,-17.018 4.5,-17 22.337,-16.192 16.785,-15.243 8.84,-15.113 23.125,-14.825 -29.21,-14.478 24.447,-13.453 -29,-13.25 42.792,-12.356 35.114,-11.59 36.385,-11.568 26.917,-10.832 24.765,-9.779 -0.26,-9.631 28.042,-9.093 35.135,-9.068 36.635,-9.068 0.889,-8.763 2.141,-8.518 8.474,-8.38 23.487,-7.714 42.03,-7.657 -4.447,-7.585 30.219,-6.768 19,-6.75 -31.391,-6.538 5.21,-6.39 34.918,-6.133 8.255,-5.715 -29.8,-5.462 -3.199,-5.01 -31.42,-4.947 -5.976,-4.863 -11.303,-4.318 -17.914,-4.101 36.322,-4.064 -16.009,-3.974 10.473,-3.958 34.925,-3.937 37.592,-3.937 12.142,-3.57 22.429,-3.175 24.715,-3.048 17.349,-2.965 -30.988,-2.794 -4.059,-2.183 -19.875,-1.925 13.589,-1.651 27.813,-1.524 35.179,-1.397 36.576,-1.397 -17.67,-1.304 37.846,-1.27 3.458,-1.19 4.695,-1.149 15.75,0 36.061,0.09 -11.347,0.605 17.139,0.82 32.938,1.053 15.75,1.5 28.067,2.286 -11.861,2.413 30.601,2.755 13.764,2.849 32.004,3.175 -31.304,4.358 -11.811,5.207 -4.5,5.25 -2,6 27.045,6.311 -30.662,8.267 21.59,9.271 28.321,9.271 -23,9.5 15.494,9.779 4.914,10.165 16.866,11.198 0.5,11.25 8.358,11.91 -17.703,12.25 -26.035,12.624 -24.256,12.617 -10.095,13.195 24.257,14.224 31.489,14.695 -31,14.75 29.235,14.819 -24.408,15.611 -27.53,15.864 -2.23,15.96 29.33,16.727 -24.25,17 -3.86,17.145 -25,17.75 24.233,20.067 21.846,21.169 -1.27,22.352 1.143,22.352
  other v2: -18.5,12.25
NetC4_2: C4.2 R16.1 U2.15 | length 8.2
  Top Layer, Top w0.5: U2.15@19.596,-4.25 R16.1@25.95,-4.25 ; C4.2@25.95,-6.25 C4.2@26,-6.2 26.075,-6.125 26.075,-4.575 R16.1@26.15,-4.5
NetC5_2: C5.2 R14.1 R16.2 R17.1 R48.1 | length 19.3
  Top Layer, Top w0.5: R16.2@27.85,-4.5 29.044,-4.5 ; R16.2@27.925,-4.625 27.925,-6.125 C5.2@28,-6.2 ; R48.1@29.337,1.397 R48.1@29.337,1.182 29.337,-4.207 29.044,-4.5 ; R17.1@31.735,-10.068 31.735,-5.048 31.187,-4.5 ; R14.1@32.297,-2.413 32.258,-2.452 32.258,-3.429 31.187,-4.5 ; 29.044,-4.5 30.916,-4.5 31.187,-4.5
NetC6_1: C6.1 U3.3 | length 3.7
  Top Layer, Top w0.2: U3.3@-19.5,4.5 -19.5,3.752 -18.859,3.111 -18.351,3.111 -17.885,2.645 -17.885,2.048 C6.1@-17.663,1.826
NetC7_2: C7.2 C8.2 C9.2 R21.2 R22.2 T2.2 U3.20 | length 20.7
  Top Layer, Top w0.6: -23.902,2.652 -21.601,4.953 -21.147,4.953 -21.1,5
  Top Layer, Top w1: C8.2@-27.125,-1.27 C9.2@-25.058,-1.27 ; C8.2@-27.025,-1.025 C7.2@-27.025,1.366 ; C8.2@-26.875,-1.016 C9.2@-24.853,-1.016 ; C9.2@-25.003,-1.266 -24.8,-1.266 T2.2@-24.8,-3.4 ; T2.2@-24.925,-3.625 R21.2@-23.025,-3.625 ; R22.2@-24.903,1.016 -24.903,1.116 -25.003,1.216 -26.875,1.216 C7.2@-27.025,1.366 ; -23.902,2.652 -26.098,2.652 -27.025,1.725 -27.025,1.475 C7.2@-27.025,1.366
NetC10_2: C10.2 U3.11 | length 4.5
  Top Layer, Top w0.2: U3.11@-18.7,7.5 -16.75,7.5 -16,8.25 C10.2@-16,9.7
NetC12_1: C12.1 pad.1@-14,20 pad.1@-17.5,20 U3.14 | length 18.2
  Top Layer, Top w0.2: v1(-20.25,10.25) -20.25,8.747 -19.9,8.397 U3.14@-19.9,7.5
  Bottom Layer, Bottom w1: v1(-20.25,10.25) -20.25,15.25 -16.5,19 -16.5,19.259 -15.963,19.796 C12.1@-15.963,20.037 ; pad.1@-17.75,20.25 -16.053,20.25 -16.053,20.228 C12.1@-15.9,20.075 ; C12.1@-15.509,20.037 -14.441,20.037 -14.037,20.037 pad.1@-14,20 ; pad.1@-14.441,20.091 pad.1@-14.441,20.384
NetC13_2: C13.2 C14.2 C15.2 R13.2 R31.2 R46.2 U3.15 | length 46
  Top Layer, Top w0.2: C14.2@-21.8,11 -21.8,9.693 -20.3,8.193 U3.15@-20.3,7.5
  Top Layer, Top w0.6: C15.2@-29,11.05 C15.2@-28.95,11 ; R13.2@-14.467,4.064 v1(-13.208,4.064) ; R46.2@-3,11.4 -2.988,11.412 -2.988,12.738 v2(-2.976,12.75)
  Top Layer, Top w1: C15.2@-29.081,11.032 -26.032,11.032 -26,11 -25.993,11.007 C14.2@-22.5,11.007 ; C14.2@-22.5,11.05 C14.2@-21.8,11.05 ; C14.2@-21.814,11.05 C14.2@-21.8,11.05 ; R31.2@-14.224,11.441 -14.124,11.441 -14.024,11.541 -14.024,12.726 v1(-14,12.75) -14.414,13.164 -14.45,13.164 -15.036,13.75 -19.114,13.75 -21.65,11.214 -21.65,11.2 C14.2@-21.8,11.05
  Bottom Layer, Bottom w0.6: v1(-13.208,4.064) -13.208,4.163 -13.5,4.455 -13.5,6.388 -14,6.888 v1(-14,12.75) -11.167,12.75 -10.167,11.75 -4,11.75 v2@-2.804,12.946
NetC17_1: C17.1 R38.1 R39.2 U4.4 | length 10.1
  Top Layer, Top w0.5: C17.1@-0.85,2.54 -0.85,4.572 -0.759,4.663 -0.759,5.852 0.65,7.26 0.65,7.55 1.1,8 1.1,7.95 1.3,7.75 3.4,7.75 4.2,8.55 U4.4@4.2,8.8
NetC17_2: C17.2 R36.2 R37.2 R38.2 R45.2 U4.1 | length 12.8
  Top Layer, Top w0.5: R45.2@0.846,-5.379 0.846,-2.594 R37.2@0.9,-2.54 R36.2@0.9,0 0.85,0.05 C17.2@0.85,2.54 R38.2@0.85,4.674 1.05,4.874 1.05,5.907 1.343,6.2 U4.1@2.3,6.2
NetIC1_3: IC1.3 R30.1 | length 3
  Top Layer, Top w0.4: R30.1@7.5,13.65 7.55,13.65 7.8,13.4 7.8,13.35 8.285,12.865 IC1.3@10.1,12.865
NetIC1_7: IC1.7 R29.1 | length 4.3
  Top Layer, Top w0.5: IC1.7@14.9,14.135 R29.1@19.25,14.135
NetJ1_1: J1.1 R14.2 | length 7.8
  Top Layer, Top w0.5: R14.2@33.997,-2.413 41.628,-2.413 J1.1@41.755,-2.54
NetJ2_1: J2.1 R17.2 | length 5
  Top Layer, Top w0.5: R17.2@33.535,-10.068 33.535,-10.168 33.885,-10.518 34.128,-10.518 34.178,-10.568 J2.1@38.229,-10.568
NetJ3_2: J3.2 R44.2 | length 2.6
  Top Layer, Top w0.6: R44.2@18.105,-16.02 R44.2@18.125,-16 18.13,-16.005 18.13,-18.52 J3.2@18.135,-18.525
NetJ4_3: J4.3 R40.2 | length 3.1
  Top Layer, Top w0.4: R40.2@7.5,20.162 7.612,20.162 7.8,20.35 7.8,20.625 J4.3@9.55,22.375
NetJ4_4: J4.4 R41.2 | length 2.9
  Top Layer, Top w0.4: J4.4@12.09,22.375 12.09,21.01 12.7,20.4 12.7,20.35 12.95,20.1 R41.2@13,20.1 ; R41.2@12.8,20.2 R41.2@12.945,20.345
NetJ7_2: J7.2 R42.2 | length 3
  Top Layer, Top w0.4: R42.2@19.5,20.1 19.549,20.1 19.799,20.35 19.799,20.799 20.75,21.75 20.75,22.27 J7.2@20.98,22.5
NetJ7_3: J7.3 R43.2 | length 2.6
  Top Layer, Top w0.4: R43.2@22.987,20.116 22.987,21.666 23.52,22.199 J7.3@23.52,22.5
NetJ8_1: J8.1 R48.2 | length 8.7
  Top Layer, Top w0.5: R48.2@29.337,2.882 29.287,2.882 28.067,4.102 28.067,7.112 29.083,8.128 J8.1@31.595,8.128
